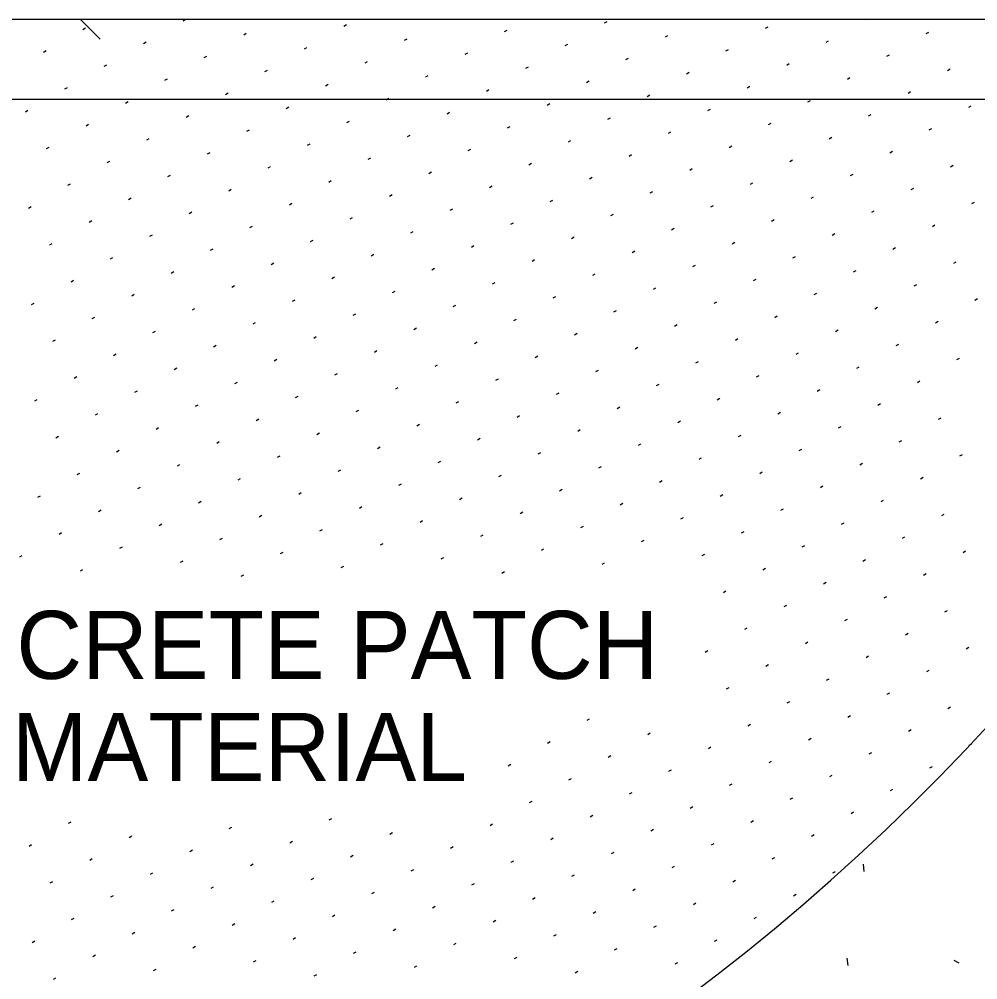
# Model space of a CAD drawing. Extents: x 99862 to 104211, y 98939 to 105076.
# Drawn here: x 102164.9 to 102390.3, y 104037.6 to 104263.5 of the extents above; entities that cross this region are included whole.
import ezdxf

# ---------------------------------------------------------------- set-up
doc = ezdxf.new("R2010")
doc.units = 0
for name, color, linetype in [('Level 1', 7, 'Continuous'), ('Level 20', 7, 'Continuous'), ('Level 3', 7, 'Continuous'), ('Level 4', 7, 'Continuous'), ('Level 6', 7, 'Continuous')]:
    doc.layers.add(name, color=color, linetype=linetype)

msp = doc.modelspace()

# ---------------------------------------------------------------- linework, layer by layer
at = {"layer": 'Level 1'}
msp.add_line((102106.49, 104263.53), (102481.5, 104263.53), dxfattribs=at)
msp.add_ellipse((102063.85, 104535.63), major_axis=(0, -590.4), ratio=0.83118, start_param=0, end_param=1.074783, dxfattribs=at)
msp.add_ellipse((102063.85, 104535.63), major_axis=(0, -590.4), ratio=0.83118, start_param=0, end_param=1.074783, dxfattribs=at)
at = {"layer": 'Level 3'}
for p, q in [((102203.4, 104263.18), (102204, 104263.53)), ((102302.54, 104262.68), (102303.14, 104263.03)), ((102363.88, 104263.46), (102364, 104263.53)), ((102179.86, 104261.14), (102180.47, 104261.49)), ((102217.66, 104259.87), (102218.27, 104260.22)), ((102241.2, 104261.91), (102241.81, 104262.26)), ((102279, 104260.64), (102279.61, 104260.99)), ((102340.34, 104261.42), (102340.95, 104261.77)), ((102378.14, 104260.15), (102378.75, 104260.5)), ((102194.13, 104257.83), (102194.74, 104258.18)), ((102255.47, 104258.6), (102256.07, 104258.95)), ((102316.81, 104259.37), (102317.41, 104259.72)), ((102354.61, 104258.11), (102355.21, 104258.46)), ((102170.59, 104255.79), (102171.2, 104256.14)), ((102231.93, 104256.56), (102232.54, 104256.91)), ((102269.73, 104255.29), (102270.34, 104255.64)), ((102293.27, 104257.33), (102293.88, 104257.68)), ((102331.07, 104256.06), (102331.68, 104256.41)), ((102208.4, 104254.52), (102209, 104254.87)), ((102246.2, 104253.25), (102246.81, 104253.6)), ((102307.54, 104254.02), (102308.14, 104254.37)), ((102368.88, 104254.8), (102369.48, 104255.15)), ((102184.86, 104252.48), (102185.47, 104252.83)), ((102222.66, 104251.21), (102223.27, 104251.56)), ((102284, 104251.98), (102284.61, 104252.33)), ((102321.81, 104250.71), (102322.41, 104251.06)), ((102345.34, 104252.75), (102345.95, 104253.1)), ((102383.14, 104251.49), (102383.75, 104251.84)), ((102199.13, 104249.17), (102199.74, 104249.52)), ((102260.47, 104249.94), (102261.07, 104250.29)), ((102298.27, 104248.67), (102298.88, 104249.02)), ((102359.61, 104249.45), (102360.21, 104249.8)), ((102175.59, 104247.13), (102176.2, 104247.48)), ((102236.93, 104247.9), (102237.54, 104248.25)), ((102274.73, 104246.63), (102275.34, 104246.98)), ((102336.07, 104247.4), (102336.68, 104247.75)), ((102213.4, 104245.86), (102214, 104246.21)), ((102251.2, 104244.59), (102251.81, 104244.94)), ((102312.54, 104245.36), (102313.14, 104245.71)), ((102350.34, 104244.09), (102350.95, 104244.44)), ((102373.88, 104246.14), (102374.48, 104246.49)), ((102166.33, 104241.78), (102166.93, 104242.13)), ((102189.86, 104243.82), (102190.47, 104244.17)), ((102227.66, 104242.55), (102228.27, 104242.9)), ((102289, 104243.32), (102289.61, 104243.67)), ((102326.81, 104242.05), (102327.41, 104242.4)), ((102388.14, 104242.83), (102388.75, 104243.18)), ((102204.13, 104240.51), (102204.74, 104240.86)), ((102265.47, 104241.28), (102266.07, 104241.63)), ((102303.27, 104240.01), (102303.88, 104240.36)), ((102364.61, 104240.79), (102365.21, 104241.14)), ((102180.59, 104238.47), (102181.2, 104238.82)), ((102218.4, 104237.2), (102219, 104237.55)), ((102241.93, 104239.24), (102242.54, 104239.59)), ((102279.73, 104237.97), (102280.34, 104238.32)), ((102341.07, 104238.74), (102341.68, 104239.09)), ((102378.88, 104237.48), (102379.48, 104237.83)), ((102194.86, 104235.16), (102195.47, 104235.51)), ((102256.2, 104235.93), (102256.81, 104236.28)), ((102317.54, 104236.7), (102318.14, 104237.05)), ((102355.34, 104235.43), (102355.95, 104235.78)), ((102171.33, 104233.12), (102171.93, 104233.47)), ((102232.66, 104233.89), (102233.27, 104234.24)), ((102270.47, 104232.62), (102271.07, 104232.97)), ((102294, 104234.66), (102294.61, 104235.01)), ((102331.81, 104233.39), (102332.41, 104233.74)), ((102209.13, 104231.85), (102209.74, 104232.2)), ((102246.93, 104230.58), (102247.54, 104230.93)), ((102308.27, 104231.35), (102308.88, 104231.7)), ((102369.61, 104232.12), (102370.21, 104232.47)), ((102185.59, 104229.81), (102186.2, 104230.16)), ((102223.4, 104228.54), (102224, 104228.89)), ((102284.73, 104229.31), (102285.34, 104229.66)), ((102346.07, 104230.08), (102346.68, 104230.43)), ((102383.88, 104228.82), (102384.48, 104229.17)), ((102199.86, 104226.5), (102200.47, 104226.85)), ((102261.2, 104227.27), (102261.81, 104227.62)), ((102299, 104226), (102299.61, 104226.35)), ((102322.54, 104228.04), (102323.14, 104228.39)), ((102360.34, 104226.77), (102360.95, 104227.12)), ((102176.33, 104224.46), (102176.93, 104224.81)), ((102237.66, 104225.23), (102238.27, 104225.58)), ((102275.47, 104223.96), (102276.07, 104224.31)), ((102336.81, 104224.73), (102337.41, 104225.08)), ((102214.13, 104223.19), (102214.74, 104223.54)), ((102251.93, 104221.92), (102252.54, 104222.27)), ((102313.27, 104222.69), (102313.88, 104223.04)), ((102351.07, 104221.42), (102351.68, 104221.77)), ((102374.61, 104223.46), (102375.21, 104223.81)), ((102167.06, 104219.11), (102167.66, 104219.46)), ((102190.59, 104221.15), (102191.2, 104221.5)), ((102228.4, 104219.88), (102229, 104220.23)), ((102289.73, 104220.65), (102290.34, 104221)), ((102327.54, 104219.38), (102328.14, 104219.73)), ((102388.88, 104220.16), (102389.48, 104220.51)), ((102204.86, 104217.84), (102205.47, 104218.19)), ((102266.2, 104218.61), (102266.81, 104218.96)), ((102304, 104217.34), (102304.61, 104217.69)), ((102365.34, 104218.11), (102365.95, 104218.46)), ((102181.33, 104215.8), (102181.93, 104216.15)), ((102242.66, 104216.57), (102243.27, 104216.92)), ((102280.47, 104215.3), (102281.07, 104215.65)), ((102341.81, 104216.07), (102342.41, 104216.42)), ((102379.61, 104214.8), (102380.21, 104215.15)), ((102195.59, 104212.49), (102196.2, 104212.84)), ((102219.13, 104214.53), (102219.74, 104214.88)), ((102256.93, 104213.26), (102257.54, 104213.61)), ((102318.27, 104214.03), (102318.88, 104214.38)), ((102356.07, 104212.76), (102356.68, 104213.11)), ((102172.06, 104210.45), (102172.66, 104210.8)), ((102233.4, 104211.22), (102234, 104211.57)), ((102294.73, 104211.99), (102295.34, 104212.34)), ((102332.54, 104210.72), (102333.14, 104211.07)), ((102209.86, 104209.18), (102210.47, 104209.53)), ((102247.66, 104207.91), (102248.27, 104208.26)), ((102271.2, 104209.95), (102271.81, 104210.3)), ((102309, 104208.68), (102309.61, 104209.03)), ((102370.34, 104209.45), (102370.95, 104209.8)), ((102186.33, 104207.14), (102186.93, 104207.49)), ((102224.13, 104205.87), (102224.74, 104206.22)), ((102285.47, 104206.64), (102286.07, 104206.99)), ((102346.81, 104207.41), (102347.41, 104207.76)), ((102384.61, 104206.14), (102385.21, 104206.49)), ((102200.59, 104203.83), (102201.2, 104204.18)), ((102261.93, 104204.6), (102262.54, 104204.95)), ((102299.73, 104203.33), (102300.34, 104203.68)), ((102323.27, 104205.37), (102323.88, 104205.72)), ((102361.07, 104204.1), (102361.68, 104204.45)), ((102177.06, 104201.78), (102177.66, 104202.13)), ((102238.4, 104202.56), (102239, 104202.91)), ((102276.2, 104201.29), (102276.81, 104201.64)), ((102337.54, 104202.06), (102338.14, 104202.41)), ((102214.86, 104200.52), (102215.47, 104200.87)), ((102252.66, 104199.25), (102253.27, 104199.6)), ((102314, 104200.02), (102314.61, 104200.37)), ((102351.81, 104198.75), (102352.41, 104199.1)), ((102375.34, 104200.79), (102375.95, 104201.14)), ((102191.33, 104198.48), (102191.93, 104198.83)), ((102229.13, 104197.21), (102229.74, 104197.56)), ((102290.47, 104197.98), (102291.07, 104198.33)), ((102328.27, 104196.71), (102328.88, 104197.06)), ((102389.61, 104197.48), (102390.21, 104197.83)), ((102167.79, 104196.43), (102168.4, 104196.78)), ((102205.59, 104195.17), (102206.2, 104195.52)), ((102266.93, 104195.94), (102267.54, 104196.29)), ((102304.73, 104194.67), (102305.34, 104195.02)), ((102366.07, 104195.44), (102366.68, 104195.79)), ((102182.06, 104193.12), (102182.66, 104193.47)), ((102243.4, 104193.9), (102244, 104194.25)), ((102281.2, 104192.63), (102281.81, 104192.98)), ((102342.54, 104193.4), (102343.14, 104193.75)), ((102380.34, 104192.13), (102380.95, 104192.48)), ((102196.33, 104189.81), (102196.93, 104190.16)), ((102219.86, 104191.86), (102220.47, 104192.21)), ((102257.66, 104190.59), (102258.27, 104190.94)), ((102319, 104191.36), (102319.61, 104191.71)), ((102356.81, 104190.09), (102357.41, 104190.44)), ((102172.79, 104187.77), (102173.4, 104188.12)), ((102234.13, 104188.55), (102234.74, 104188.9)), ((102295.47, 104189.32), (102296.07, 104189.67)), ((102333.27, 104188.05), (102333.88, 104188.4)), ((102210.59, 104186.51), (102211.2, 104186.86)), ((102248.4, 104185.24), (102249, 104185.59)), ((102271.93, 104187.28), (102272.54, 104187.63)), ((102309.73, 104186.01), (102310.34, 104186.36)), ((102371.07, 104186.78), (102371.68, 104187.13)), ((102187.06, 104184.46), (102187.66, 104184.81)), ((102224.86, 104183.2), (102225.47, 104183.55)), ((102286.2, 104183.97), (102286.81, 104184.32)), ((102347.54, 104184.74), (102348.14, 104185.09)), ((102385.34, 104183.47), (102385.95, 104183.82)), ((102201.33, 104181.15), (102201.93, 104181.5)), ((102262.66, 104181.93), (102263.27, 104182.28)), ((102300.47, 104180.66), (102301.07, 104181.01)), ((102324, 104182.7), (102324.61, 104183.05)), ((102361.81, 104181.43), (102362.41, 104181.78)), ((102177.79, 104179.11), (102178.4, 104179.46)), ((102239.13, 104179.89), (102239.74, 104180.24)), ((102276.93, 104178.62), (102277.54, 104178.97)), ((102338.27, 104179.39), (102338.88, 104179.74)), ((102215.59, 104177.85), (102216.2, 104178.2)), ((102253.4, 104176.58), (102254, 104176.93)), ((102314.73, 104177.35), (102315.34, 104177.7)), ((102376.07, 104178.12), (102376.68, 104178.47)), ((102192.06, 104175.8), (102192.66, 104176.15)), ((102229.86, 104174.54), (102230.47, 104174.89)), ((102291.2, 104175.31), (102291.81, 104175.66)), ((102329, 104174.04), (102329.61, 104174.39)), ((102352.54, 104176.08), (102353.14, 104176.43)), ((102168.52, 104173.76), (102169.13, 104174.11)), ((102206.33, 104172.49), (102206.93, 104172.84)), ((102267.66, 104173.27), (102268.27, 104173.62)), ((102305.47, 104172), (102306.07, 104172.35)), ((102366.81, 104172.77), (102367.41, 104173.12)), ((102182.79, 104170.45), (102183.4, 104170.8)), ((102244.13, 104171.23), (102244.74, 104171.58)), ((102281.93, 104169.96), (102282.54, 104170.31)), ((102343.27, 104170.73), (102343.88, 104171.08)), ((102381.07, 104169.46), (102381.68, 104169.81)), ((102197.06, 104167.14), (102197.66, 104167.49)), ((102220.59, 104169.18), (102221.2, 104169.53)), ((102258.4, 104167.92), (102259, 104168.27)), ((102319.73, 104168.69), (102320.34, 104169.04)), ((102357.54, 104167.42), (102358.14, 104167.77)), ((102173.52, 104165.1), (102174.13, 104165.45)), ((102234.86, 104165.88), (102235.47, 104166.23)), ((102296.2, 104166.65), (102296.81, 104167)), ((102334, 104165.38), (102334.61, 104165.73)), ((102211.33, 104163.83), (102211.93, 104164.18)), ((102272.66, 104164.61), (102273.27, 104164.96)), ((102310.47, 104163.34), (102311.07, 104163.69)), ((102371.81, 104164.11), (102372.41, 104164.46)), ((102187.79, 104161.79), (102188.4, 104162.14)), ((102225.59, 104160.52), (102226.2, 104160.87)), ((102249.13, 104162.57), (102249.74, 104162.92)), ((102286.93, 104161.3), (102287.54, 104161.65)), ((102348.27, 104162.07), (102348.88, 104162.42)), ((102386.07, 104160.8), (102386.68, 104161.15)), ((102202.06, 104158.48), (102202.66, 104158.83)), ((102263.4, 104159.26), (102264, 104159.61)), ((102324.73, 104160.03), (102325.34, 104160.38)), ((102362.54, 104158.76), (102363.14, 104159.11)), ((102178.52, 104156.44), (102179.13, 104156.79)), ((102239.86, 104157.22), (102240.47, 104157.57)), ((102277.66, 104155.95), (102278.27, 104156.3)), ((102301.2, 104157.99), (102301.81, 104158.34)), ((102339, 104156.72), (102339.61, 104157.07)), ((102216.33, 104155.17), (102216.93, 104155.52)), ((102254.13, 104153.91), (102254.74, 104154.26)), ((102315.47, 104154.68), (102316.07, 104155.03)), ((102376.81, 104155.45), (102377.41, 104155.8)), ((102192.79, 104153.13), (102193.4, 104153.48)), ((102230.59, 104151.86), (102231.2, 104152.21)), ((102291.93, 104152.64), (102292.54, 104152.99)), ((102329.73, 104151.37), (102330.34, 104151.72)), ((102353.27, 104153.41), (102353.88, 104153.76)), ((102169.26, 104151.09), (102169.86, 104151.44)), ((102207.06, 104149.82), (102207.66, 104150.17)), ((102268.4, 104150.6), (102269, 104150.95)), ((102306.2, 104149.33), (102306.81, 104149.68)), ((102367.54, 104150.1), (102368.14, 104150.45)), ((102183.52, 104147.78), (102184.13, 104148.13)), ((102244.86, 104148.55), (102245.47, 104148.9)), ((102282.66, 104147.29), (102283.27, 104147.64)), ((102344, 104148.06), (102344.61, 104148.41)), ((102381.81, 104146.79), (102382.41, 104147.14)), ((102221.33, 104146.51), (102221.93, 104146.86)), ((102259.13, 104145.25), (102259.74, 104145.6)), ((102320.47, 104146.02), (102321.07, 104146.37)), ((102358.27, 104144.75), (102358.88, 104145.1)), ((102174.26, 104142.43), (102174.86, 104142.78)), ((102197.79, 104144.47), (102198.4, 104144.82)), ((102235.59, 104143.2), (102236.2, 104143.55)), ((102296.93, 104143.98), (102297.54, 104144.33)), ((102334.73, 104142.71), (102335.34, 104143.06)), ((102212.06, 104141.16), (102212.66, 104141.51)), ((102273.4, 104141.94), (102274, 104142.29)), ((102311.2, 104140.67), (102311.81, 104141.02)), ((102372.54, 104141.44), (102373.14, 104141.79)), ((102188.52, 104139.12), (102189.13, 104139.47)), ((102226.33, 104137.85), (102226.93, 104138.2)), ((102249.86, 104139.89), (102250.47, 104140.24)), ((102287.66, 104138.63), (102288.27, 104138.98)), ((102349, 104139.4), (102349.61, 104139.75)), ((102386.81, 104138.13), (102387.41, 104138.48)), ((102164.99, 104137.08), (102165.59, 104137.43)), ((102202.79, 104135.81), (102203.4, 104136.16)), ((102264.13, 104136.59), (102264.74, 104136.94)), ((102325.47, 104137.36), (102326.07, 104137.71)), ((102363.27, 104136.09), (102363.88, 104136.44)), ((102179.26, 104133.77), (102179.86, 104134.12)), ((102240.59, 104134.54), (102241.2, 104134.89)), ((102278.4, 104133.28), (102279, 104133.63)), ((102301.93, 104135.32), (102302.54, 104135.67)), ((102339.73, 104134.05), (102340.34, 104134.4)), ((102217.06, 104132.5), (102217.66, 104132.85)), ((102377.54, 104132.78), (102378.14, 104133.13)), ((102330.47, 104128.7), (102331.07, 104129.05)), ((102354, 104130.74), (102354.61, 104131.09)), ((102368.27, 104127.43), (102368.88, 104127.78)), ((102344.73, 104125.39), (102345.34, 104125.74)), ((102359, 104122.08), (102359.61, 104122.43)), ((102382.54, 104124.12), (102383.14, 104124.47)), ((102335.47, 104120.04), (102336.07, 104120.39)), ((102373.27, 104118.77), (102373.88, 104119.12)), ((102349.73, 104116.73), (102350.34, 104117.08)), ((102387.54, 104115.46), (102388.14, 104115.81)), ((102326.2, 104114.69), (102326.81, 104115.04)), ((102364, 104113.42), (102364.61, 104113.77)), ((102340.47, 104111.38), (102341.07, 104111.73)), ((102378.27, 104110.11), (102378.88, 104110.46)), ((102354.73, 104108.07), (102355.34, 104108.42)), ((102331.2, 104106.03), (102331.81, 104106.38)), ((102369, 104104.76), (102369.61, 104105.11)), ((102345.47, 104102.72), (102346.07, 104103.07)), ((102359.73, 104099.41), (102360.34, 104099.76)), ((102383.27, 104101.45), (102383.88, 104101.8)), ((102298.4, 104098.63), (102299, 104098.98)), ((102336.2, 104097.37), (102336.81, 104097.72)), ((102312.66, 104095.32), (102313.27, 104095.67)), ((102374, 104096.1), (102374.61, 104096.45)), ((102289.13, 104093.28), (102289.74, 104093.63)), ((102350.47, 104094.06), (102351.07, 104094.41)), ((102388.27, 104092.79), (102388.88, 104093.14)), ((102326.93, 104092.02), (102327.54, 104092.37)), ((102364.73, 104090.75), (102365.34, 104091.1)), ((102303.4, 104089.97), (102304, 104090.32)), ((102341.2, 104088.71), (102341.81, 104089.06)), ((102279.86, 104087.93), (102280.47, 104088.28)), ((102317.66, 104086.66), (102318.27, 104087.01)), ((102379, 104087.44), (102379.61, 104087.79)), ((102294.13, 104084.62), (102294.74, 104084.97)), ((102355.47, 104085.4), (102356.07, 104085.75)), ((102308.4, 104081.31), (102309, 104081.66)), ((102331.93, 104083.36), (102332.54, 104083.71)), ((102369.73, 104082.09), (102370.34, 104082.44)), ((102284.86, 104079.27), (102285.47, 104079.62)), ((102346.2, 104080.05), (102346.81, 104080.4)), ((102322.66, 104078), (102323.27, 104078.35)), ((102360.47, 104076.74), (102361.07, 104077.09)), ((102237.79, 104075.19), (102238.4, 104075.54)), ((102299.13, 104075.96), (102299.74, 104076.31)), ((102336.93, 104074.69), (102337.54, 104075.04)), ((102176.45, 104074.42), (102177.06, 104074.77)), ((102214.26, 104073.15), (102214.86, 104073.5)), ((102275.59, 104073.92), (102276.2, 104074.27)), ((102313.4, 104072.65), (102314, 104073)), ((102190.72, 104071.11), (102191.33, 104071.46)), ((102252.06, 104071.88), (102252.66, 104072.23)), ((102289.86, 104070.61), (102290.47, 104070.96)), ((102351.2, 104071.39), (102351.81, 104071.74)), ((102167.18, 104069.07), (102167.79, 104069.42)), ((102204.99, 104067.8), (102205.59, 104068.15)), ((102228.52, 104069.84), (102229.13, 104070.19)), ((102266.33, 104068.57), (102266.93, 104068.92)), ((102327.66, 104069.34), (102328.27, 104069.69)), ((102181.45, 104065.76), (102182.06, 104066.11)), ((102242.79, 104066.53), (102243.4, 104066.88)), ((102304.13, 104067.3), (102304.74, 104067.65)), ((102341.93, 104066.03), (102342.54, 104066.38)), ((102219.26, 104064.49), (102219.86, 104064.84)), ((102257.06, 104063.22), (102257.66, 104063.57)), ((102280.59, 104065.26), (102281.2, 104065.61)), ((102318.4, 104063.99), (102319, 104064.34)), ((102195.72, 104062.45), (102196.33, 104062.8)), ((102233.52, 104061.18), (102234.13, 104061.53)), ((102294.86, 104061.95), (102295.47, 104062.3)), ((102356.2, 104062.73), (102356.81, 104063.08)), ((102172.18, 104060.41), (102172.79, 104060.76)), ((102209.99, 104059.14), (102210.59, 104059.49)), ((102271.33, 104059.91), (102271.93, 104060.26)), ((102332.66, 104060.68), (102333.27, 104061.03)), ((102186.45, 104057.1), (102187.06, 104057.45)), ((102247.79, 104057.87), (102248.4, 104058.22)), ((102285.59, 104056.6), (102286.2, 104056.95)), ((102309.13, 104058.64), (102309.74, 104058.99)), ((102346.93, 104057.37), (102347.54, 104057.72)), ((102224.26, 104055.83), (102224.86, 104056.18)), ((102262.06, 104054.56), (102262.66, 104054.91)), ((102323.4, 104055.33), (102324, 104055.68)), ((102200.72, 104053.79), (102201.33, 104054.14)), ((102238.52, 104052.52), (102239.13, 104052.87)), ((102299.86, 104053.29), (102300.47, 104053.64)), ((102337.66, 104052.02), (102338.27, 104052.37)), ((102177.18, 104051.75), (102177.79, 104052.1)), ((102214.99, 104050.48), (102215.59, 104050.83)), ((102276.33, 104051.25), (102276.93, 104051.6)), ((102314.13, 104049.98), (102314.74, 104050.33)), ((102191.45, 104048.44), (102192.06, 104048.79)), ((102252.79, 104049.21), (102253.4, 104049.56)), ((102290.59, 104047.94), (102291.2, 104048.29)), ((102167.92, 104046.4), (102168.52, 104046.75)), ((102205.72, 104045.13), (102206.33, 104045.48)), ((102229.26, 104047.17), (102229.86, 104047.52)), ((102267.06, 104045.9), (102267.66, 104046.25)), ((102328.4, 104046.67), (102329, 104047.02)), ((102182.18, 104043.09), (102182.79, 104043.44)), ((102243.52, 104043.86), (102244.13, 104044.21)), ((102304.86, 104044.63), (102305.47, 104044.98)), ((102219.99, 104041.82), (102220.59, 104042.17)), ((102281.33, 104042.59), (102281.93, 104042.94)), ((102319.13, 104041.32), (102319.74, 104041.67)), ((102196.45, 104039.78), (102197.06, 104040.13)), ((102234.26, 104038.51), (102234.86, 104038.86)), ((102257.79, 104040.55), (102258.4, 104040.9)), ((102295.59, 104039.28), (102296.2, 104039.63)), ((102172.92, 104037.74), (102173.52, 104038.09))]:
    msp.add_line(p, q, dxfattribs=at)
at = {"layer": 'Level 4'}
for p, q in [((102363.6, 104063.07), (102363.42, 104064.81)), ((102359.77, 104040.94), (102359.59, 104042.68)), ((102384.68, 104042.19), (102385.83, 104041.63))]:
    msp.add_line(p, q, dxfattribs=at)
at = {"layer": 'Level 6'}
for p, q in [((102183.94, 104258.81), (102179.22, 104263.53)), ((102647.84, 104244.65), (101394.64, 104244.65))]:
    msp.add_line(p, q, dxfattribs=at)

# ---------------------------------------------------------------- texts
at = {"layer": 'Level 20'}
for s, p in [('CONCRETE PATCH', (102116.66, 104108.38)), ('MATERIAL', (102163.14, 104084.38))]:
    msp.add_text(s, height=16, dxfattribs=at).set_placement(p)

doc.saveas('drawing.dxf')
